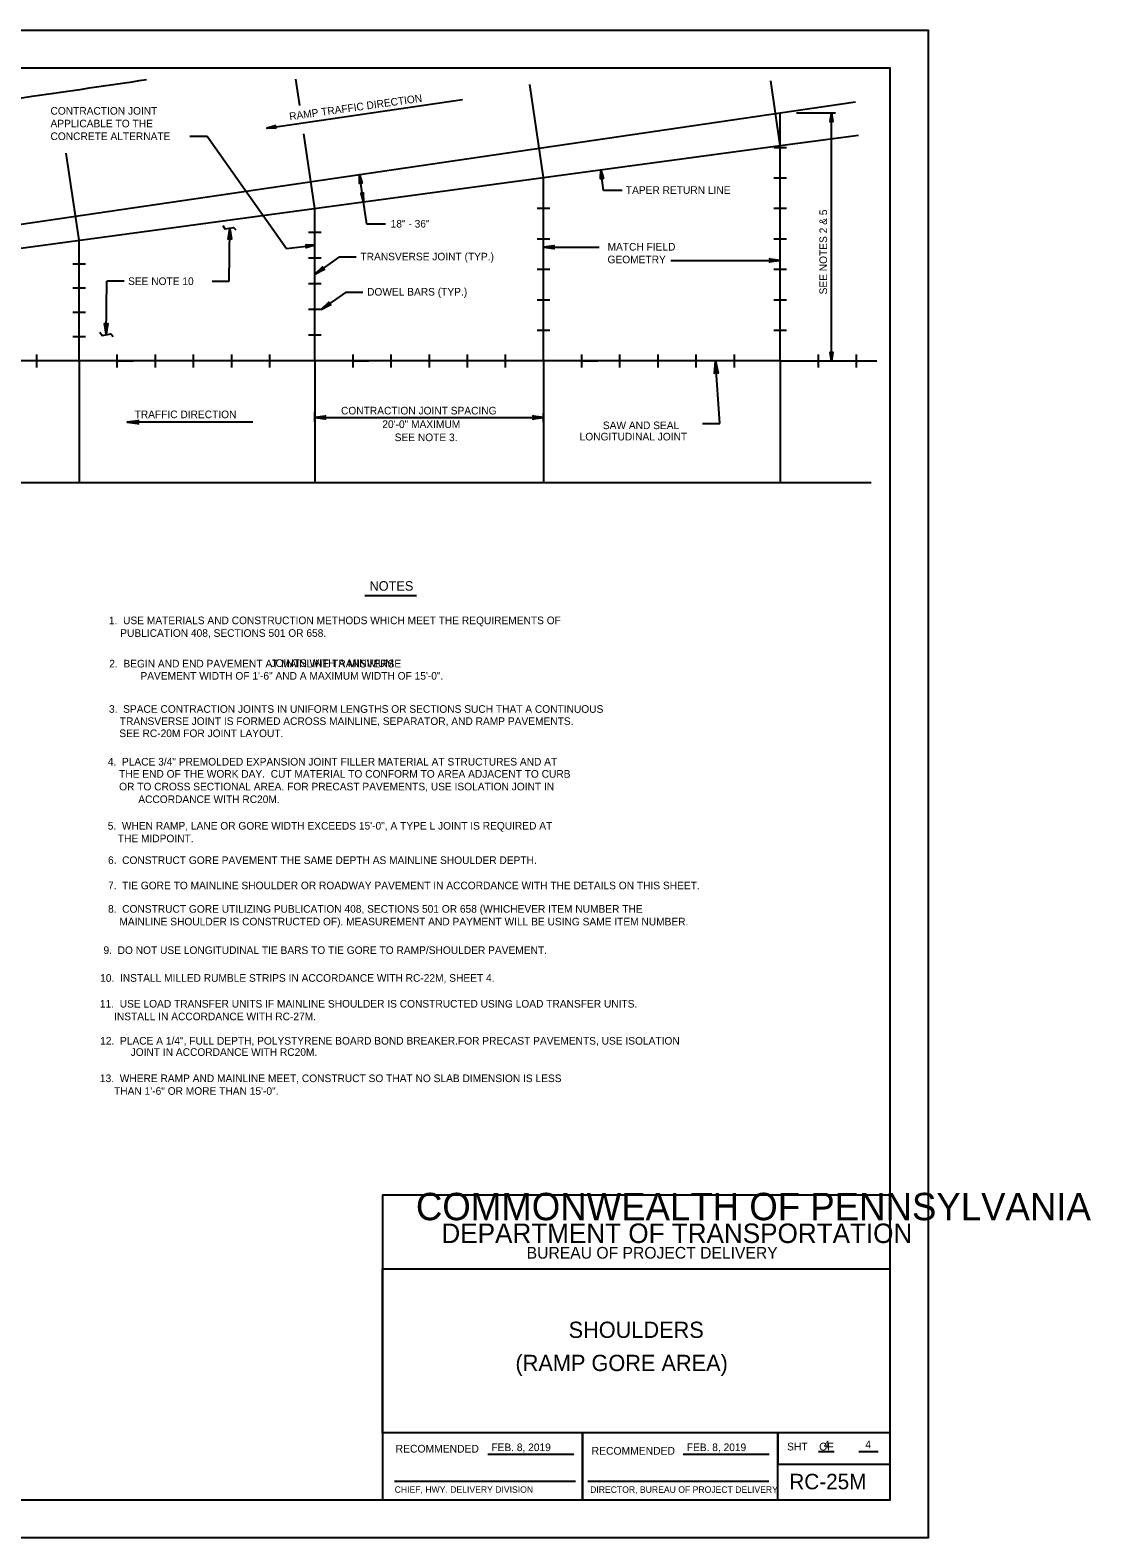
# Model space of a CAD drawing. Extents: x 638216 to 639962, y 297510 to 299292.
# Drawn here: x 639544 to 639962, y 298698 to 299292 of the extents above; entities that cross this region are included whole.
import ezdxf

# ---------------------------------------------------------------- set-up
doc = ezdxf.new("R2010")
doc.units = 0
for name, color, linetype in [('1', 7, 'Continuous'), ('2', 7, 'Continuous'), ('3', 7, 'Continuous'), ('PLT-BNDY', 7, 'Continuous')]:
    doc.layers.add(name, color=color, linetype=linetype)

msp = doc.modelspace()

# ---------------------------------------------------------------- linework, layer by layer
at = {"layer": '1'}
for p, q in [((639650.29, 299262.56), (639648.76, 299272.95)), ((639746.37, 299234.16), (639741, 299270.84)), ((639839.61, 299246.75), (639835.86, 299272.31)), ((639292.33, 299179.55), (639839.61, 299259.6)), ((639656.23, 299222), (639651.91, 299251.44)), ((639292.35, 299172.88), (639839.61, 299246.75)), ((639839.61, 299246.75), (639870.39, 299250.9)), ((639563.31, 299209.45), (639558.29, 299243.71)), ((639746.37, 299233.93), (639746.37, 299233.93)), ((639839.61, 299233.93), (639839.61, 299233.93)), ((639746.37, 299221.93), (639746.37, 299221.93)), ((639839.61, 299221.93), (639839.61, 299221.93)), ((639622.52, 299193.28), (639622.75, 299214.11)), ((639656.23, 299212.54), (639656.23, 299212.54)), ((639746.37, 299209.92), (639746.37, 299209.92)), ((639839.61, 299209.92), (639839.61, 299209.92)), ((639645.11, 299206.28), (639656.23, 299207.51)), ((639563.31, 299200.1), (639563.31, 299200.1)), ((639665.65, 299202.79), (639656.13, 299196.02)), ((639656.23, 299202.41), (639656.23, 299202.41)), ((639746.37, 299197.92), (639746.37, 299197.92)), ((639839.61, 299197.92), (639839.61, 299197.92)), ((639574, 299172.46), (639574.23, 299193.28)), ((639656.23, 299192.28), (639656.23, 299192.28)), ((639563.31, 299190.55), (639563.31, 299190.55)), ((639668.26, 299188.93), (639658.74, 299182.16)), ((639563.31, 299181), (639563.31, 299181)), ((639656.23, 299182.16), (639656.23, 299182.16)), ((639746.37, 299185.91), (639746.37, 299185.91)), ((639839.61, 299185.91), (639839.61, 299185.91)), ((639563.31, 299171.45), (639563.31, 299171.45)), ((639656.23, 299172.03), (639656.23, 299172.03)), ((639746.37, 299173.91), (639746.37, 299173.91)), ((639839.61, 299173.91), (639839.61, 299173.91)), ((639578.34, 299161.9), (639584.61, 299161.9)), ((639671.27, 299161.9), (639677.53, 299161.9)), ((639761.41, 299161.9), (639767.67, 299161.9)), ((639815.77, 299137.21), (639814.12, 299161.9)), ((639839.61, 299161.9), (639877.63, 299161.9)), ((639724.35, 298731.23), (639758.24, 298731.23)), ((639801.35, 298731.23), (639835.22, 298731.23)), ((639854.75, 298732.21), (639860.89, 298732.21)), ((639870.56, 298732.21), (639878.21, 298732.21)), ((639687.65, 298720.56), (639758.9, 298720.56)), ((639763.82, 298720.56), (639835.16, 298720.56))]:
    msp.add_line(p, q, dxfattribs=at)
for points in [[(639882.88, 298713.24), (639882.88, 299277.24), (639096.88, 299277.24), (639096.88, 298713.24), (639882.88, 298713.24), (639882.88, 298739.6), (639682.88, 298739.6), (639682.88, 298804.28), (639882.88, 298804.28), (639882.88, 298833.24), (639682.88, 298833.24), (639682.88, 298713.24), (639761.69, 298713.24), (639761.69, 298739.6), (639761.69, 298713.24), (639838.69, 298713.24), (639838.69, 298739.6), (639838.69, 298727.28), (639882.88, 298727.28)], [(639882.88, 298713.24), (639882.88, 299277.24), (639096.88, 299277.24), (639096.88, 298713.24), (639882.88, 298713.24), (639882.88, 298739.6), (639682.88, 298739.6), (639682.88, 298804.28), (639882.88, 298804.28), (639882.88, 298833.24), (639682.88, 298833.24), (639682.88, 298713.24), (639761.69, 298713.24), (639761.69, 298739.6), (639761.69, 298713.24), (639838.69, 298713.24), (639838.69, 298739.6), (639838.69, 298727.28), (639882.88, 298727.28)], [(639882.88, 298713.24), (639882.88, 299277.24), (639096.88, 299277.24), (639096.88, 298713.24), (639882.88, 298713.24), (639882.88, 298739.6), (639682.88, 298739.6), (639682.88, 298804.28), (639882.88, 298804.28), (639882.88, 298833.24), (639682.88, 298833.24), (639682.88, 298713.24), (639761.69, 298713.24), (639761.69, 298739.6), (639761.69, 298713.24), (639838.69, 298713.24), (639838.69, 298739.6), (639838.69, 298727.28), (639882.88, 298727.28)], [(639882.88, 298713.24), (639882.88, 299277.24), (639096.88, 299277.24), (639096.88, 298713.24), (639882.88, 298713.24), (639882.88, 298739.6), (639682.88, 298739.6), (639682.88, 298804.28), (639882.88, 298804.28), (639882.88, 298833.24), (639682.88, 298833.24), (639682.88, 298713.24), (639761.69, 298713.24), (639761.69, 298739.6), (639761.69, 298713.24), (639838.69, 298713.24), (639838.69, 298739.6), (639838.69, 298727.28), (639882.88, 298727.28)], [(639882.88, 298713.24), (639882.88, 299277.24), (639096.88, 299277.24), (639096.88, 298713.24), (639882.88, 298713.24), (639882.88, 298739.6), (639682.88, 298739.6), (639682.88, 298804.28), (639882.88, 298804.28), (639882.88, 298833.24), (639682.88, 298833.24), (639682.88, 298713.24), (639761.69, 298713.24), (639761.69, 298739.6), (639761.69, 298713.24), (639838.69, 298713.24), (639838.69, 298739.6), (639838.69, 298727.28), (639882.88, 298727.28)], [(639882.88, 298713.24), (639882.88, 299277.24), (639096.88, 299277.24), (639096.88, 298713.24), (639882.88, 298713.24), (639882.88, 298739.6), (639682.88, 298739.6), (639682.88, 298804.28), (639882.88, 298804.28), (639882.88, 298833.24), (639682.88, 298833.24), (639682.88, 298713.24), (639761.69, 298713.24), (639761.69, 298739.6), (639761.69, 298713.24), (639838.69, 298713.24), (639838.69, 298739.6), (639838.69, 298727.28), (639882.88, 298727.28)], [(639619.9, 299215.26), (639620.73, 299213.98), (639624.16, 299214.55), (639625.07, 299213.52)], [(639571.53, 299173.28), (639572.36, 299171.99), (639575.79, 299172.56), (639576.7, 299171.53)], [(639813.85, 299157.26), (639814.17, 299157.45), (639814.12, 299161.9), (639813.85, 299157.26), (639813.66, 299157.01), (639814.12, 299161.9), (639814.64, 299157.49), (639814.98, 299157.35), (639814.12, 299161.9), (639815.21, 299157.11), (639814.98, 299157.35)]]:
    msp.add_lwpolyline(points, dxfattribs=at)
at = {"layer": '2'}
for p, q in [((639637.26, 299253.63), (639714.37, 299264.97)), ((639839.61, 299259.6), (639869.3, 299263.95)), ((639839.61, 299161.9), (639839.61, 299259.28)), ((639846, 299259.6), (639861.35, 299259.6)), ((639859.82, 299161.88), (639859.82, 299259.6)), ((639606.97, 299250.48), (639613.78, 299250.48)), ((639613.78, 299250.48), (639645.11, 299206.28)), ((639842.11, 299245.94), (639837.1, 299245.94)), ((639746.37, 299161.9), (639746.37, 299234.16)), ((639842.11, 299233.93), (639837.1, 299233.93)), ((639777.37, 299229.08), (639770.03, 299229.08)), ((639656.23, 299161.9), (639656.23, 299222)), ((639748.88, 299221.93), (639743.87, 299221.93)), ((639842.11, 299221.93), (639837.1, 299221.93)), ((639684.02, 299215.82), (639676.68, 299215.82)), ((639658.74, 299212.54), (639653.73, 299212.54)), ((639748.88, 299209.92), (639743.87, 299209.92)), ((639842.11, 299209.92), (639837.1, 299209.92)), ((639563.31, 299161.9), (639563.31, 299209.45)), ((639746.37, 299206.75), (639768.31, 299206.75)), ((639565.81, 299200.1), (639560.8, 299200.1)), ((639658.74, 299202.41), (639653.73, 299202.41)), ((639672.46, 299202.79), (639665.65, 299202.79)), ((639748.88, 299197.92), (639743.87, 299197.92)), ((639796.55, 299201.51), (639839.61, 299201.51)), ((639842.11, 299197.92), (639837.1, 299197.92)), ((639581.04, 299193.28), (639574.23, 299193.28)), ((639615.71, 299193.28), (639622.52, 299193.28)), ((639658.74, 299192.28), (639653.73, 299192.28)), ((639565.81, 299190.55), (639560.8, 299190.55)), ((639675.07, 299188.93), (639668.26, 299188.93)), ((639565.81, 299181), (639560.8, 299181)), ((639658.74, 299182.16), (639653.73, 299182.16)), ((639748.88, 299185.91), (639743.87, 299185.91)), ((639842.11, 299185.91), (639837.1, 299185.91)), ((639565.81, 299171.45), (639560.8, 299171.45)), ((639658.74, 299172.03), (639653.73, 299172.03)), ((639748.88, 299173.91), (639743.87, 299173.91)), ((639842.11, 299173.91), (639837.1, 299173.91)), ((639546.64, 299159.39), (639546.64, 299164.41)), ((639578.34, 299159.39), (639578.34, 299164.41)), ((639593.38, 299159.39), (639593.38, 299164.41)), ((639608.41, 299159.39), (639608.41, 299164.41)), ((639623.45, 299159.39), (639623.45, 299164.41)), ((639638.48, 299159.39), (639638.48, 299164.41)), ((639671.27, 299159.39), (639671.27, 299164.41)), ((639686.3, 299159.39), (639686.3, 299164.41)), ((639701.34, 299159.39), (639701.34, 299164.41)), ((639716.37, 299159.39), (639716.37, 299164.41)), ((639731.41, 299159.39), (639731.41, 299164.41)), ((639761.41, 299159.39), (639761.41, 299164.41)), ((639776.44, 299159.39), (639776.44, 299164.41)), ((639791.48, 299159.39), (639791.48, 299164.41)), ((639806.51, 299159.39), (639806.51, 299164.41)), ((639821.55, 299159.39), (639821.55, 299164.41)), ((639854.64, 299159.39), (639854.64, 299164.41)), ((639869.68, 299159.39), (639869.68, 299164.41)), ((639839.61, 299161.9), (639292.35, 299161.9)), ((639563.31, 299161.9), (639563.31, 299113.9)), ((639656.23, 299161.9), (639656.23, 299113.9)), ((639746.37, 299161.9), (639746.37, 299113.9)), ((639839.61, 299161.9), (639839.61, 299113.9)), ((639656.23, 299137.87), (639656.23, 299141.76)), ((639656.23, 299139.63), (639746.37, 299139.63)), ((639746.37, 299137.84), (639746.37, 299141.3)), ((639631.74, 299137.81), (639582.3, 299137.81)), ((639808.95, 299137.21), (639815.77, 299137.21)), ((639875.5, 299113.9), (639120.56, 299113.9)), ((639696.27, 299069.34), (639675.89, 299069.34))]:
    msp.add_line(p, q, dxfattribs=at)
for points in [[(639859.41, 299256.27), (639859.64, 299256.39), (639859.82, 299259.6), (639859.41, 299256.27), (639859.25, 299256.09), (639859.82, 299259.6), (639859.98, 299256.39), (639860.21, 299256.27), (639859.82, 299259.6), (639860.38, 299256.09), (639860.21, 299256.27)], [(639640.61, 299253.7), (639640.47, 299253.93), (639637.26, 299253.63), (639640.61, 299253.7), (639640.82, 299253.58), (639637.26, 299253.63), (639640.4, 299254.25), (639640.49, 299254.5), (639637.26, 299253.63), (639640.65, 299254.69), (639640.49, 299254.5)], [(639673.89, 299232), (639674.1, 299232.14), (639673.82, 299235.35), (639673.89, 299232), (639673.76, 299231.79), (639673.82, 299235.35), (639674.44, 299232.19), (639674.69, 299232.11), (639673.82, 299235.35), (639674.87, 299231.96), (639674.69, 299232.11)], [(639768.92, 299233.84), (639769.13, 299233.99), (639768.85, 299237.2), (639768.92, 299233.84), (639768.79, 299233.64), (639768.85, 299237.2), (639769.47, 299234.04), (639769.71, 299233.96), (639768.85, 299237.2), (639769.9, 299233.8), (639769.71, 299233.96)], [(639674.5, 299227.82), (639674.75, 299227.74), (639675.4, 299224.58), (639674.5, 299227.82), (639674.32, 299227.98), (639675.4, 299224.58), (639675.09, 299227.79), (639675.3, 299227.93), (639675.4, 299224.58), (639675.43, 299228.14), (639675.3, 299227.93)], [(639622.25, 299210.11), (639622.52, 299210.25), (639622.75, 299214.11), (639622.25, 299210.11), (639622.06, 299209.89), (639622.75, 299214.11), (639622.94, 299210.25), (639623.21, 299210.11), (639622.75, 299214.11), (639623.41, 299209.89), (639623.21, 299210.11)], [(639652.88, 299207.51), (639653.02, 299207.29), (639656.23, 299207.51), (639652.88, 299207.51), (639652.68, 299207.64), (639656.23, 299207.51), (639653.06, 299206.95), (639652.98, 299206.71), (639656.23, 299207.51), (639652.82, 299206.53), (639652.98, 299206.71)], [(639750.37, 299206.25), (639750.23, 299206.53), (639746.37, 299206.75), (639750.37, 299206.25), (639750.59, 299206.06), (639746.37, 299206.75), (639750.23, 299206.94), (639750.37, 299207.21), (639746.37, 299206.75), (639750.59, 299207.41), (639750.37, 299207.21)], [(639659.68, 299197.93), (639659.4, 299198.07), (639656.13, 299196.02), (639659.68, 299197.93), (639659.97, 299197.9), (639656.13, 299196.02), (639659.17, 299198.41), (639659.12, 299198.72), (639656.13, 299196.02), (639659.19, 299199), (639659.12, 299198.72)], [(639835.61, 299202), (639835.75, 299201.73), (639839.61, 299201.51), (639835.61, 299202), (639835.39, 299202.2), (639839.61, 299201.51), (639835.75, 299201.31), (639835.61, 299201.04), (639839.61, 299201.51), (639835.39, 299200.85), (639835.61, 299201.04)], [(639662.28, 299184.06), (639662.01, 299184.21), (639658.74, 299182.16), (639662.28, 299184.06), (639662.57, 299184.03), (639658.74, 299182.16), (639661.77, 299184.54), (639661.73, 299184.85), (639658.74, 299182.16), (639661.79, 299185.13), (639661.73, 299184.85)], [(639574.5, 299176.46), (639574.22, 299176.32), (639574, 299172.46), (639574.5, 299176.46), (639574.69, 299176.68), (639574, 299172.46), (639573.81, 299176.32), (639573.53, 299176.46), (639574, 299172.46), (639573.34, 299176.68), (639573.53, 299176.46)], [(639860.24, 299165.21), (639860.01, 299165.09), (639859.82, 299161.88), (639860.24, 299165.21), (639860.4, 299165.39), (639859.82, 299161.88), (639859.66, 299165.09), (639859.43, 299165.21), (639859.82, 299161.88), (639859.27, 299165.39), (639859.43, 299165.21)], [(639586.47, 299137.28), (639586.31, 299137.58), (639582.3, 299137.81), (639586.47, 299137.28), (639586.68, 299137.1), (639582.3, 299137.81), (639586.31, 299138.02), (639586.45, 299138.32), (639582.3, 299137.81), (639586.68, 299138.5), (639586.45, 299138.32)], [(639660.23, 299139.14), (639660.09, 299139.41), (639656.23, 299139.63), (639660.23, 299139.14), (639660.45, 299138.95), (639656.23, 299139.63), (639660.09, 299139.83), (639660.23, 299140.1), (639656.23, 299139.63), (639660.45, 299140.29), (639660.23, 299140.1)], [(639742.38, 299140.13), (639742.52, 299139.86), (639746.37, 299139.63), (639742.38, 299140.13), (639742.16, 299140.32), (639746.37, 299139.63), (639742.52, 299139.44), (639742.38, 299139.17), (639746.37, 299139.63), (639742.16, 299138.97), (639742.38, 299139.17)]]:
    msp.add_lwpolyline(points, dxfattribs=at)
msp.add_spline([(639171.79, 299211.48), (639544.88, 299266.17), (639589.83, 299272.75)], degree=3, dxfattribs=at)
at = {"layer": '3'}
for p, q in [((639675.4, 299224.58), (639673.82, 299235.35)), ((639770.03, 299229.08), (639768.85, 299237.2)), ((639676.68, 299215.82), (639675.4, 299224.58))]:
    msp.add_line(p, q, dxfattribs=at)
at = {"layer": 'PLT-BNDY'}
msp.add_lwpolyline([(639056.88, 299292.24), (639897.88, 299292.24), (639897.88, 298698.24), (639056.88, 298698.24)], close=True, dxfattribs=at)

# ---------------------------------------------------------------- texts
at = {"layer": '1'}
for s, height, p in [('CONTRACTION JOINT', 3, (639552.05, 299258.95)), ('APPLICABLE TO THE', 3, (639552.05, 299253.95)), ('CONCRETE ALTERNATE', 3, (639552.05, 299248.95)), ('COMMONWEALTH OF PENNSYLVANIA', 10.7834, (639696.04, 298823.38)), ('DEPARTMENT OF TRANSPORTATION', 7.6843, (639706.1, 298814.39)), ('BUREAU OF PROJECT DELIVERY', 4.6221, (639739.69, 298808.23)), ('SHOULDERS', 6.4, (639756.21, 298777.01)), ('RECOMMENDED', 3.048, (639688.05, 298731.83)), ('FEB. 8, 2019', 3, (639725.79, 298732.41)), ('FEB. 8, 2019', 3, (639802.79, 298732.41)), ('SHT    OF', 3.048, (639842.29, 298732.67)), ('4', 3.05, (639856.79, 298733.51)), ('4', 3.05, (639873.15, 298733.51)), ('APPROVED', 0.0192, (639725.91, 298731.17)), ('RECOMMENDED', 3.048, (639765.29, 298731)), ('RC-25M', 6.096, (639843.21, 298717.37)), ('CHIEF, HWY. DELIVERY DIVISION', 2.54, (639687.68, 298716)), ('DIRECTOR, BUREAU OF PROJECT DELIVERY', 2.54, (639764.7, 298715.97))]:
    msp.add_text(s, height=height, dxfattribs=at).set_placement(p)
at = {"layer": '3'}
for s, rotation, p in [('RAMP TRAFFIC DIRECTION', 8, (639646.34, 299256.72)), ('SEE NOTES 2 & 5', 90, (639858.06, 299188.12))]:
    msp.add_text(s, height=3, rotation=rotation, dxfattribs=at).set_placement(p)
for s, height, p in [('TAPER RETURN LINE', 3, (639778.77, 299227.73)), ('18" - 36"', 3, (639686.09, 299214.47)), ('TRANSVERSE JOINT (TYP.) ', 3, (639674.2, 299201.53)), ('MATCH FIELD', 3, (639771.56, 299205.39)), ('GEOMETRY', 3, (639771.56, 299200.39)), ('SEE NOTE 10', 3, (639582.61, 299191.83)), ('DOWEL BARS (TYP.) ', 3, (639676.8, 299187.66)), ('TRAFFIC DIRECTION', 3, (639585.19, 299139.37)), ('CONTRACTION JOINT SPACING', 3, (639666.53, 299140.84)), ('20\'-0" MAXIMUM', 3, (639682.81, 299135.49)), ('SEE NOTE 3.', 3, (639687.68, 299130.32)), ('LONGITUDINAL JOINT', 3, (639760.57, 299130.6)), ('SAW AND SEAL', 3, (639769.71, 299135.04)), ('NOTES', 3.75, (639677.76, 299071.4)), ('1.  USE MATERIALS AND CONSTRUCTION METHODS WHICH MEET THE REQUIREMENTS OF', 3, (639575.08, 299058.2)), ('    PUBLICATION 408, SECTIONS 501 OR 658.', 3, (639575.08, 299053.21)), ('2.  BEGIN AND END PAVEMENT AT MAINLINE TRANSVERSE', 3, (639575.2, 299041.16)), ('                                              JOINTS WITH A MINIMUM', 3, (639587.48, 299041.35)), ('PAVEMENT WIDTH OF 1\'-6" AND A MAXIMUM WIDTH OF 15\'-0".', 3, (639587.48, 299036.35)), ('3.  SPACE CONTRACTION JOINTS IN UNIFORM LENGTHS OR SECTIONS SUCH THAT A CONTINUOUS', 3, (639575.1, 299023.29)), ('    TRANSVERSE JOINT IS FORMED ACROSS MAINLINE, SEPARATOR, AND RAMP PAVEMENTS.', 3, (639574.91, 299018.5)), ('    SEE RC-20M FOR JOINT LAYOUT.', 3, (639574.71, 299013.71)), ('4.  PLACE 3/4" PREMOLDED EXPANSION JOINT FILLER MATERIAL AT STRUCTURES AND AT', 3, (639574.64, 299002.52)), ('    THE END OF THE WORK DAY.  CUT MATERIAL TO CONFORM TO AREA ADJACENT TO CURB', 3, (639574.64, 298997.73)), ('    OR TO CROSS SECTIONAL AREA. FOR PRECAST PAVEMENTS, USE ISOLATION JOINT IN ', 3, (639574.64, 298992.73)), ('ACCORDANCE WITH RC20M.', 3, (639586.64, 298987.73)), ('5.  WHEN RAMP, LANE OR GORE WIDTH EXCEEDS 15\'-0", A TYPE L JOINT IS REQUIRED AT', 3, (639574.61, 298977.27)), ('    THE MIDPOINT.', 3, (639574.12, 298972.29)), ('6.  CONSTRUCT GORE PAVEMENT THE SAME DEPTH AS MAINLINE SHOULDER DEPTH.', 3, (639574.71, 298963.72)), ('7.  TIE GORE TO MAINLINE SHOULDER OR ROADWAY PAVEMENT IN ACCORDANCE WITH THE DETAILS ON THIS SHEET.', 3, (639574.71, 298953.76)), ('8.  CONSTRUCT GORE UTILIZING PUBLICATION 408, SECTIONS 501 OR 658 (WHICHEVER ITEM NUMBER THE', 3, (639574.73, 298944.53)), ('    MAINLINE SHOULDER IS CONSTRUCTED OF). MEASUREMENT AND PAYMENT WILL BE USING SAME ITEM NUMBER.', 3, (639574.73, 298939.53)), (' 9.  DO NOT USE LONGITUDINAL TIE BARS TO TIE GORE TO RAMP/SHOULDER PAVEMENT.', 3, (639571.82, 298928.27)), ('10.  INSTALL MILLED RUMBLE STRIPS IN ACCORDANCE WITH RC-22M, SHEET 4.', 3, (639571.63, 298917.32)), ('11.  USE LOAD TRANSFER UNITS IF MAINLINE SHOULDER IS CONSTRUCTED USING LOAD TRANSFER UNITS.', 3, (639571.53, 298907.16)), ('     INSTALL IN ACCORDANCE WITH RC-27M.', 3, (639571.53, 298902.16)), ('12.  PLACE A 1/4", FULL DEPTH, POLYSTYRENE BOARD BOND BREAKER.FOR PRECAST PAVEMENTS, USE ISOLATION ', 3, (639571.63, 298892.57)), ('JOINT IN ACCORDANCE WITH RC20M.', 3, (639583.63, 298888.13)), ('13.  WHERE RAMP AND MAINLINE MEET, CONSTRUCT SO THAT NO SLAB DIMENSION IS LESS', 3, (639571.53, 298877.79)), ('     THAN 1\'-6" OR MORE THAN 15\'-0".', 3, (639571.53, 298872.79)), ('(RAMP GORE AREA)', 6.4, (639735.27, 298763.95))]:
    msp.add_text(s, height=height, dxfattribs=at).set_placement(p)

doc.saveas('drawing.dxf')
